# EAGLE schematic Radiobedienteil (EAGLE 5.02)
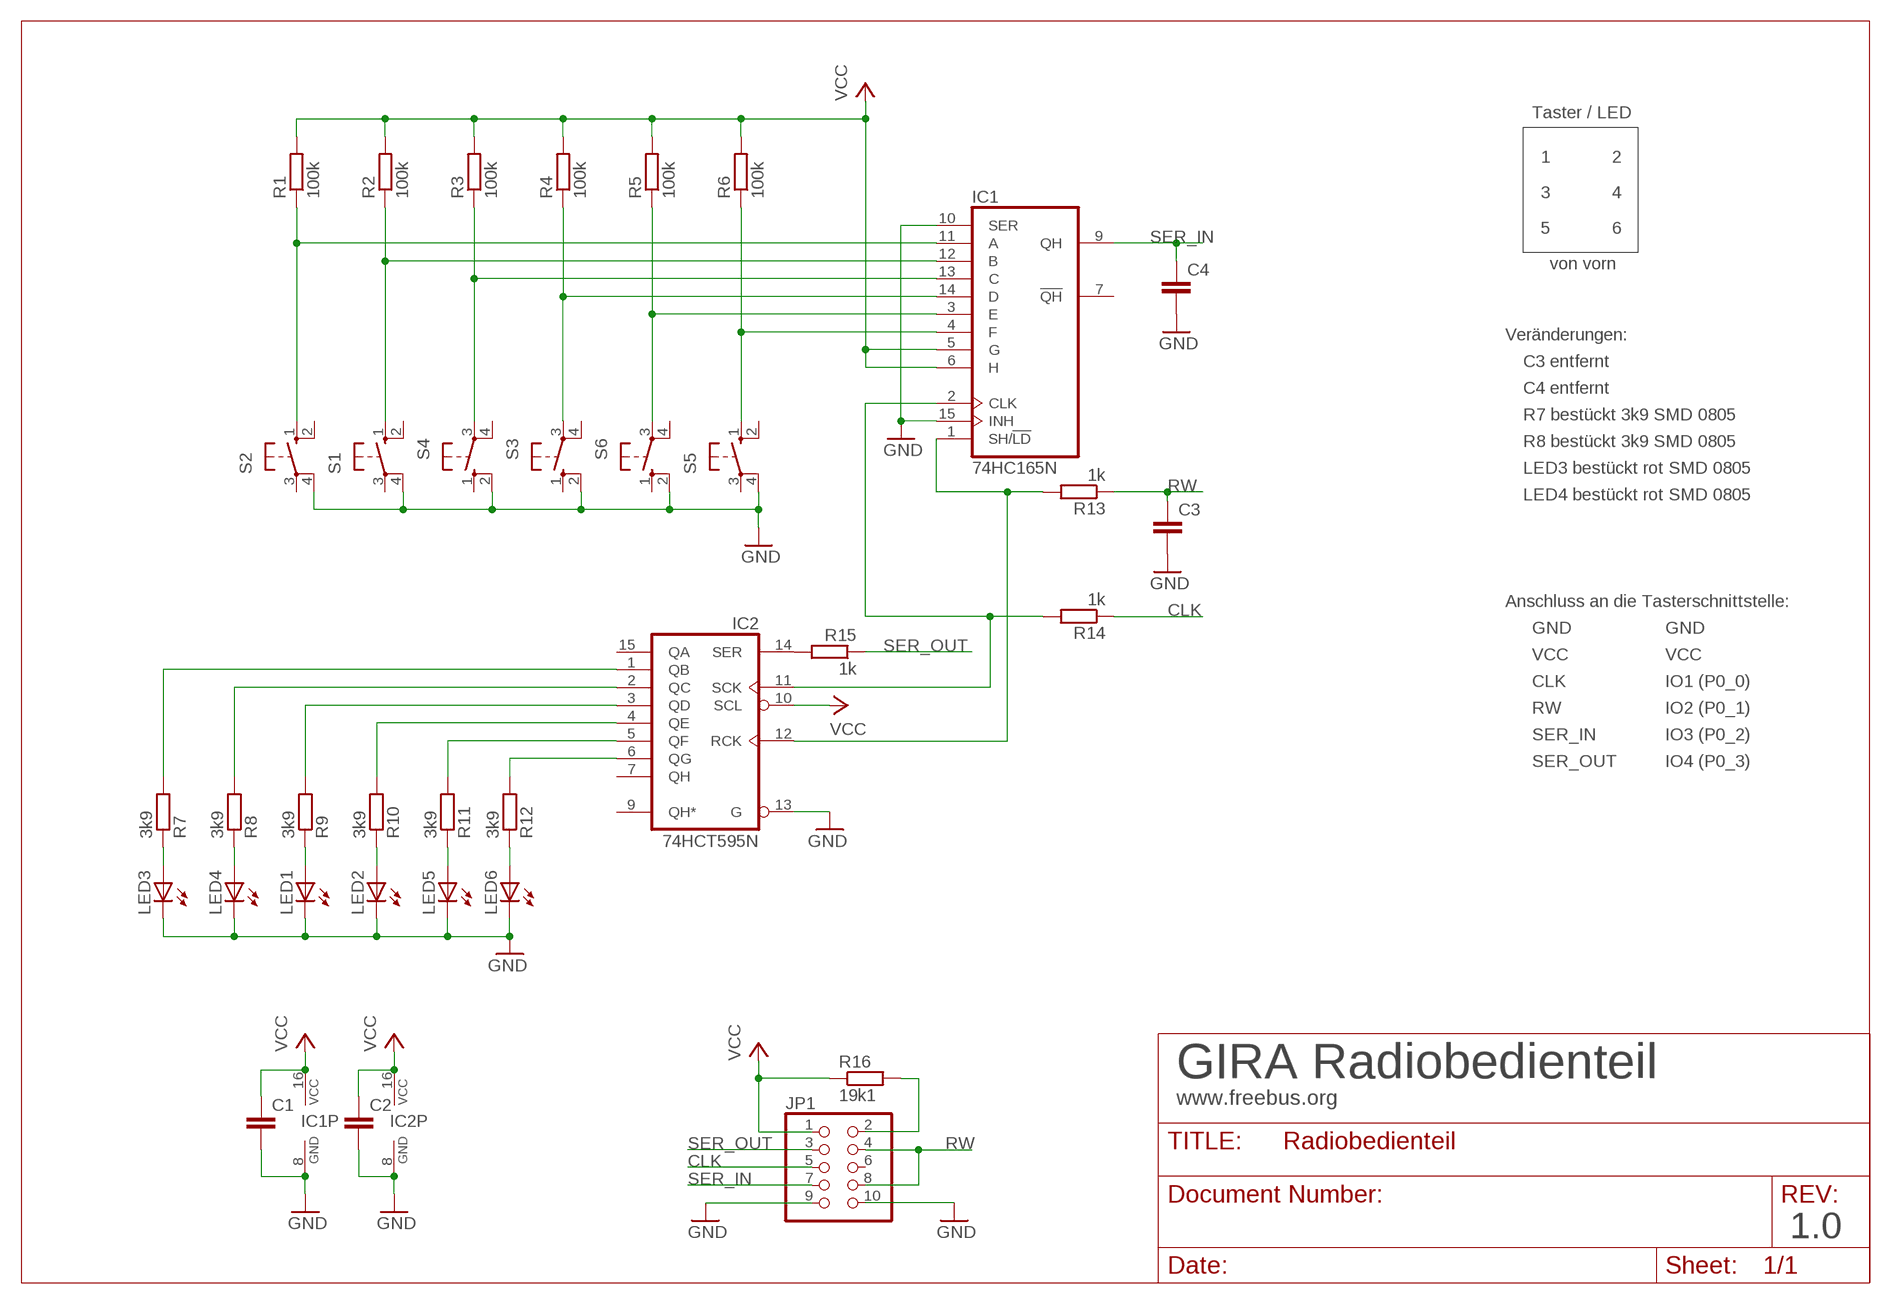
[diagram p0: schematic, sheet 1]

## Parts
C1  C-EUC0805  [C0805]
C2  C-EUC0805  [C0805]
C3  C-EUC0805  [C0805]
C4  C-EUC0805  [C0805]
IC1  74HC165N  [DIL16]
IC2  74HCT595N  [DIL16]
JP1  PINHD-2X5  [2X05]
LED1  LED3MM  [LED3MM]
LED2  LED3MM  [LED3MM]
LED3  LED3MM  [LED3MM]
LED4  LED3MM  [LED3MM]
LED5  LED3MM  [LED3MM]
LED6  LED3MM  [LED3MM]
R1  100k  R-EU_0207/15  [0207/15]
R2  100k  R-EU_0207/15  [0207/15]
R3  100k  R-EU_0207/12  [0207/12]
R4  100k  R-EU_0207/10  [0207/10]
R5  100k  R-EU_0207/15  [0207/15]
R6  100k  R-EU_0207/15  [0207/15]
R7  3k9  R-EU_0207/2V  [0207/2V]
R8  3k9  R-EU_0207/2V  [0207/2V]
R9  3k9  R-EU_0207/2V  [0207/2V]
R10  3k9  R-EU_0207/2V  [0207/2V]
R11  3k9  R-EU_0207/2V  [0207/2V]
R12  3k9  R-EU_0207/2V  [0207/2V]
R13  1k  R-EU_0207/15  [0207/15]
R14  1k  R-EU_0204/7  [0204/7]
R15  1k  R-EU_0207/15  [0207/15]
R16  19k1  R-EU_0204/7  [0204/7]
S1  10-XX  [B3F-10XX]
S2  10-XX  [B3F-10XX]
S3  10-XX  [B3F-10XX]
S4  10-XX  [B3F-10XX]
S5  10-XX  [B3F-10XX]
S6  10-XX  [B3F-10XX]

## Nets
CLK: JP1.5 R14.1
GND: C1.2 C2.2 C3.2 C4.2 IC1.8(GND) IC1.10(SER) IC1.15(INH) IC2.8(GND) IC2.13(G) JP1.9 JP1.10 LED1.K(C) LED2.K(C) LED3.K(C) LED4.K(C) LED5.K(C) LED6.K(C) S1.4(P1) S2.4(P1) S3.2(S1) S4.2(S1) S5.4(P1) S6.2(S1)
N$1: LED6.A R12.1
N$2: IC2.5(QF) R11.2
N$3: IC1.4(F) R6.1 S5.1(S)
N$4: IC1.3(E) R5.1 S6.3(P)
N$5: IC1.14(D) R4.1 S3.3(P)
N$6: IC1.13(C) R3.1 S4.3(P)
N$7: IC1.12(B) R2.1 S1.1(S)
N$8: IC1.11(A) R1.1 S2.1(S)
N$9: IC2.6(QG) R12.2
N$10: JP1.2 R16.2
N$11: LED5.A R11.1
N$12: LED2.A R10.1
N$13: LED1.A R9.1
N$14: LED4.A R8.1
N$15: LED3.A R7.1
N$16: IC1.2(CLK) IC2.11(SCK) R14.2
N$18: IC2.4(QE) R10.2
N$19: IC2.3(QD) R9.2
N$20: IC2.2(QC) R8.2
N$21: IC2.1(QB) R7.2
N$26: IC1.1(SH/!LD) IC2.12(RCK) R13.2
N$27: IC2.14(SER) R15.2
RW: C3.1 JP1.4 JP1.8 R13.1
SER_IN: C4.1 IC1.9(QH) JP1.7
SER_OUT: JP1.3 R15.1
VCC: C1.1 C2.1 IC1.5(G) IC1.6(H) IC1.16(VCC) IC2.10(SCL) IC2.16(VCC) JP1.1 R1.2 R2.2 R3.2 R4.2 R5.2 R6.2 R16.1
Unconnected: IC1.7(!QH) IC2.7(QH) IC2.9(QH*) IC2.15(QA) JP1.6 S1.2(S1) S1.3(P) S2.2(S1) S2.3(P) S3.1(S) S3.4(P1) S4.1(S) S4.4(P1) S5.2(S1) S5.3(P) S6.1(S) S6.4(P1)

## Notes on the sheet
- Taster / LED
- 1 | 2
- 3 | 4
- 5 | 6
- SER_IN
- von vorn
- Veränderungen:
- C3 entfernt
- C4 entfernt
- R7 bestückt 3k9 SMD 0805
- R8 bestückt 3k9 SMD 0805
- LED3 bestückt rot SMD 0805
- RW
- LED4 bestückt rot SMD 0805
- Anschluss an die Tasterschnittstelle:
- CLK
- GND | GND
- SER_OUT
- VCC | VCC
- CLK | IO1 (P0_0)
- RW | IO2 (P0_1)
- SER_IN | IO3 (P0_2)
- SER_OUT | IO4 (P0_3)
- GIRA Radiobedienteil
- www.freebus.org
- SER_OUT | RW
- CLK
- SER_IN
- 1.0

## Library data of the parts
C1-C4 = rcl:C-EU: CAPACITOR, European symbol
IC1 = 74xx-eu:74*165: 8-bit parallel load SHIFT REGISTER
IC2 = 74xx-eu:74*595: 8-bit SHIFT REGISTER, output latch
JP1 = pinhead:PINHD-2X5: PIN HEADER
LED1-LED6 = led:LED: LED
R1-R16 = rcl:R-EU_: RESISTOR, European symbol
S1-S6 = switch-omron:10-XX: OMRON SWITCH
